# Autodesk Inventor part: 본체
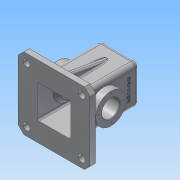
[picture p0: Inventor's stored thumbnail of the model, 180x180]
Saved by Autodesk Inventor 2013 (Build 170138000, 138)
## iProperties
Created: 2016-02
Part Number: 본체
Material: 알루미늄 6061
Document SubType Name: Modeling
Designer: Administrator
Density: 2.71 g/cm^3
Mass: 932.778 g
Surface Area: 1043.9 cm^2
Volume: 344.199 cm^3
Author: Administrator
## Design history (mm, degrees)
sketch "스케치1"
  geometry: L1 (35, -60)-(-35, -60); L2 (-35, -60)-(-35, 60); L3 (-35, 60)-(35, 60); L4 (35, 60)-(35, -60); L5 (35, -60)-(-35, 60); L6 (-35, -60)-(35, 60); 1 further point
  constraints: 12 end point, 2 midpoint, 2 parallel, 1 horizontal, 1 perpendicular
  dimensions: "d0" = 70 distance of L2.end L3.end; "d1" = 120 distance of L1.end L2.end
extrude "돌출1" new body sketch "스케치1" stored distance "d2" = 70; taper "d3" = 0 deg
feature "쉘1" dims "d4" = 5
sketch "스케치2"
  geometry: C1 r 20 at (35, 35); 1 further point
  constraints: 1 centre point, 1 coincident
  dimensions: "d5" = 40 diameter of C1
extrude "돌출2" join sketch "스케치2" distance "d6" = 10; taper "d7" = -10 deg
sketch "스케치3"
  geometry: L1 (70, 0)-(0, 0) reference; C1 r 27.5 at (35, 55); 1 further point
  constraints: 1 centre point, 1 vertical alignment
  dimensions: "d9" = 55 diameter of C1; "d10" = 55 distance from line of L1 C1.centre
extrude "돌출3" join sketch "스케치3" distance "d11" = 13; taper "d12" = 0 deg
sketch "스케치4"
  geometry: C1 r 27.5 at (30, 55) reference; C2 r 27.5 at (30, 55); 1 further point
  constraints: 1 centre point, 1 coincident
  dimensions: "d13" = 55 diameter of C2
extrude "돌출4" join sketch "스케치4" distance "d14" = 7; taper "d15" = -45 deg
sketch "스케치5"
  geometry: C1 r 27.5 at (0, 0) reference; C2 r 16 at (0, 0); 1 further point
  constraints: 1 centre point, 1 coincident
  dimensions: "d16" = 32 diameter of C2
extrude "돌출5" cut sketch "스케치5" stored distance "d17" = 7; taper "d18" = 0 deg
sketch "스케치6"
  geometry: C1 r 18.237 at (0, 0) reference; 1 further point
  constraints: 1 coincident
hole "구멍1" sketch "스케치6" at (0, 0) diameter "d19" = 21; stored, may be unused: countersink angle "d23" = 90 deg, drill point angle "d25" = 118 deg; dims "d20" = 6, "d21" = 28, "d22" = 4, "d24" = 8
sketch "스케치7"
  geometry: L1 (65, -5)-(65, -65) reference; L2 (65, -65)-(5, -65) reference; L3 (5, -65)-(5, -5) reference; L4 (5, -5)-(65, -5) reference; L5 (100, -100)-(-30, -100); L6 (-30, -100)-(-30, 30); L7 (-30, 30)-(100, 30); L8 (100, 30)-(100, -100); L9 (100, -100)-(-30, 30); L10 (-30, -100)-(100, 30); 1 further point
  constraints: 12 end point, 2 midpoint, 2 parallel, 1 horizontal, 1 perpendicular
  dimensions: "d26" = 130 distance of L6.end L7.end; "d27" = 130 distance of L5.end L6.end
extrude "돌출6" join sketch "스케치7" distance "d28" = 10; taper "d29" = 0 deg
sketch "스케치8"
  geometry: L1 (-50, 50)-(35.069, 35); L2 (-50, 35)-(60, 35) reference; L3 (-50, 65)-(-50, -65) reference; L4 (-60, 65)-(-50, 65) reference; 1 further point
  constraints: 2 end point, 2 point on line
  dimensions: "d30" = 15 distance from line of L1.start L4; "d32" = 10 deg angle of L4 L1
feature "리브1" sketch "스케치8" dims "d33" = 1, "d34" = 10, "d35" = 0, "d36" = 0, "d37" = 1, "d38" = 1
chamfer "모따기1" distance "d39" = 10; stored, may be unused: second distance "d40" = 2, angle "d41" = 45 deg
sketch "스케치9"
  geometry: L1 (90, 100)-(-20, 100) reference; L2 (100, -20)-(100, 90) reference; C1 r 6 at (-15, 85); C2 r 6 at (-15, -15); C3 r 6 at (85, -15); C4 r 6 at (85, 85); 1 further point
  constraints: 4 centre point, 2 horizontal alignment, 2 vertical alignment
  dimensions: "d42" = 12 diameter of C1; "d43" = 12 diameter of C2; "d44" = 12 diameter of C3; "d45" = 12 diameter of C4; "d46" = 100 distance of C4.centre C1.centre; "d47" = 15 distance from line of L2 C4.centre; "d48" = 100 distance of C3.centre C4.centre; "d49" = 15 distance from line of L1 C1.centre
extrude "돌출7" cut sketch "스케치9" stored distance "d50" = 10; taper "d51" = 0 deg
sketch "스케치10"
  geometry: C1 r 16 at (0, 0) reference; C2 r 27.5 at (0, 0) reference; A1 r 22.5 centre (0, 0) between (0, 22.5) and (-22.5, 0); 3 further points
  constraints: 4 point on circle, 2 vertical alignment, 1 centre point, 1 coincident, 1 horizontal alignment
  dimensions: "d52" = 45 diameter of A1
hole "구멍2" sketch "스케치10" at (0, 22.5), (-22.5, 0), (0, -22.5), (22.5, 0) diameter "d53" = 3.242; stored, may be unused: countersink angle "d57" = 90 deg, drill point angle "d59" = 118 deg; dims "d54" = 8, "d55" = 4, "d56" = 2, "d58" = 10
fillet "모깎기2" dims "d61" = 8
fillet "모깎기3" dims "d62" = 8
fillet "모깎기4" dims "d63" = 0.5
fillet "모깎기5" dims "d64" = 3
fillet "모깎기6" dims "d65" = 3
fillet "모깎기7" dims "d66" = 3
fillet "모깎기8" dims "d67" = 3
chamfer "모따기2" distance "d68" = 1; stored, may be unused: second distance "d69" = 2, angle "d70" = 45 deg
fillet "모깎기9" dims "d71" = 3
fillet "모깎기10" dims "d72" = 3
sketch "스케치11"
  geometry: L1 (8.763, 18)-(45.237, 18) reference; L2 (62, -99)-(62, 0) reference; 2 further points
  constraints: 1 other
  dimensions: "d73" = 30 distance from line of L1 point (27, -12); "d74" = 35 distance from line of point (27, -12) L2
feature "엠보싱1" sketch "스케치11" dims "d0" = 70, "d1" = 120, "d75" = 0.5, "d76" = 0
fillet "모깎기11" dims "d77" = 0.5
node "솔리드1"
mirror "대칭1"
mirror "대칭2"
mirror "대칭3"
mirror "대칭4"
